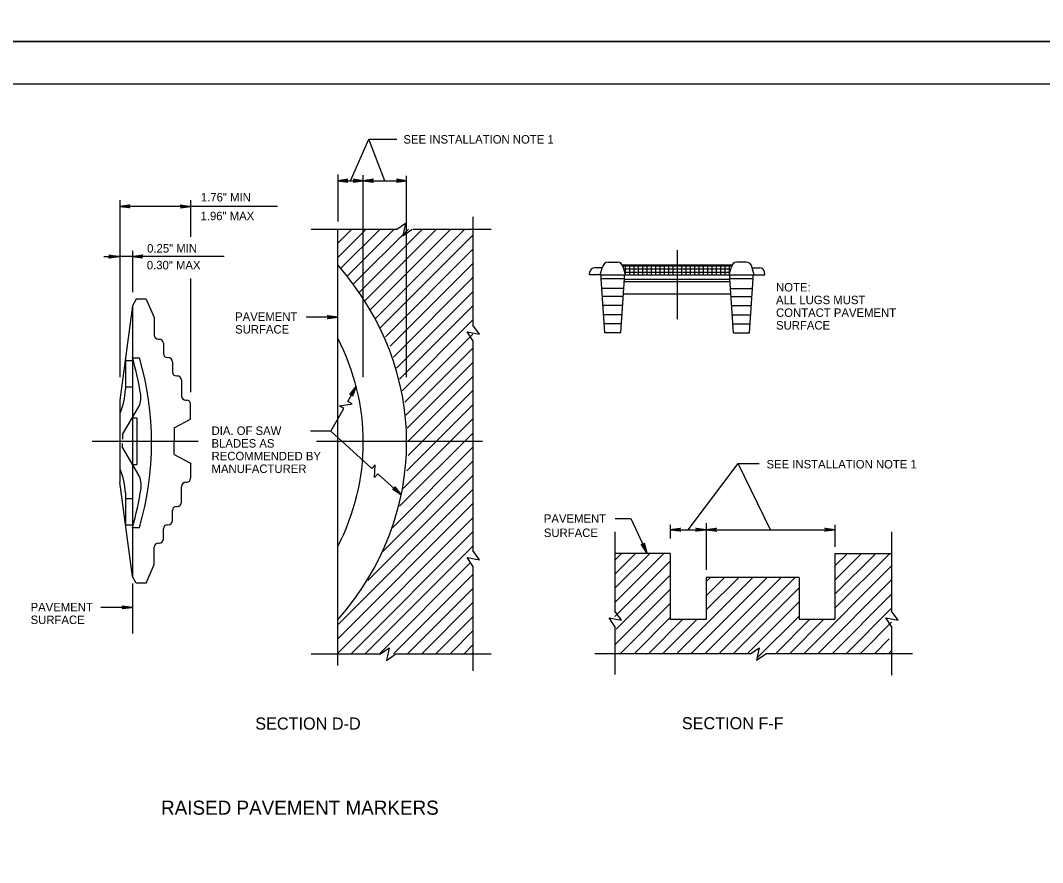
# Model space of a CAD drawing. Extents: x 639362 to 641108, y 298458 to 299646.
# Drawn here: x 640436.9 to 640799.3, y 298760.6 to 299059.1 of the extents above; entities that cross this region are included whole.
import ezdxf

# ---------------------------------------------------------------- set-up
doc = ezdxf.new("R2010")
doc.units = 0
for name, color, linetype in [('1', 7, 'Continuous'), ('2', 7, 'Continuous'), ('PLT-BNDY', 7, 'Continuous')]:
    doc.layers.add(name, color=color, linetype=linetype)

msp = doc.modelspace()

# ---------------------------------------------------------------- linework, layer by layer
at = {"layer": '1'}
msp.add_line((640243.31, 299036.63), (641029.31, 299036.63), dxfattribs=at)
at = {"layer": '2'}
for p, q in [((640553.93, 299002.33), (640560.43, 299017.03)), ((640560.43, 299017.03), (640570.32, 299017.03)), ((640566.15, 299002.33), (640560.43, 299017.03)), ((640549.4, 299004.47), (640549.4, 298987.85)), ((640558.46, 298932.66), (640558.46, 299004.34)), ((640573.84, 298932.66), (640573.84, 299004.07)), ((640549.4, 299002.33), (640558.46, 299002.33)), ((640558.46, 299002.33), (640573.84, 299002.33)), ((640472.13, 298995.38), (640472.13, 298932.71)), ((640497.22, 298995.38), (640497.22, 298982.37)), ((640528.03, 298993.14), (640472.13, 298993.14)), ((640597.33, 298989.51), (640597.33, 298951.16)), ((640539.93, 298985.17), (640570.36, 298985.17)), ((640549.4, 298985.16), (640549.41, 298985.17)), ((640549.4, 298980.15), (640554.42, 298985.17)), ((640549.4, 298975.14), (640559.43, 298985.17)), ((640549.4, 298830.51), (640549.4, 298985.17)), ((640550.44, 298971.18), (640564.44, 298985.17)), ((640552.68, 298968.41), (640569.44, 298985.17)), ((640554.92, 298965.64), (640574.45, 298985.17)), ((640556.84, 298962.55), (640579.46, 298985.17)), ((640558.75, 298959.45), (640584.47, 298985.17)), ((640560.66, 298956.35), (640589.48, 298985.17)), ((640562.56, 298953.25), (640594.49, 298985.17)), ((640570.36, 298985.17), (640573.44, 298987.22)), ((640573.44, 298987.22), (640572.53, 298982.82)), ((640572.53, 298982.82), (640575.83, 298985.17)), ((640576.1, 298985.17), (640603.86, 298985.17)), ((640564.45, 298950.13), (640597.33, 298983.01)), ((640476.61, 298977.46), (640476.61, 298962.86)), ((640566.35, 298947.02), (640597.33, 298978)), ((640669.77, 298977.68), (640669.77, 298953.22)), ((640466.45, 298975.45), (640471.88, 298975.45)), ((640509.08, 298975.45), (640472.13, 298975.45)), ((640645.29, 298973.5), (640648.59, 298973.5)), ((640694.24, 298973.5), (640690.94, 298973.5)), ((640567.97, 298943.62), (640597.33, 298972.99)), ((640638.64, 298969.01), (640638.78, 298969.98)), ((640643.2, 298971.48), (640640.53, 298971.48)), ((640642.5, 298969.01), (640643.19, 298971.43)), ((640650.27, 298972.5), (640689.27, 298972.5)), ((640650.48, 298972.11), (640689.08, 298972.11)), ((640651.38, 298969.01), (640650.68, 298971.43)), ((640651.07, 298971.07), (640688.46, 298971.07)), ((640651.07, 298969.88), (640688.46, 298969.88)), ((640651.36, 298972.11), (640651.36, 298969.01)), ((640652.9, 298972.11), (640652.9, 298969.01)), ((640654.43, 298972.11), (640654.43, 298969.01)), ((640655.96, 298972.11), (640655.96, 298969.01)), ((640657.5, 298972.11), (640657.5, 298969.01)), ((640659.03, 298972.11), (640659.03, 298969.01)), ((640660.56, 298972.11), (640660.56, 298969.01)), ((640662.1, 298972.11), (640662.1, 298969.01)), ((640663.63, 298972.11), (640663.63, 298969.01)), ((640665.17, 298972.11), (640665.17, 298969.01)), ((640666.7, 298972.11), (640666.7, 298969.01)), ((640668.23, 298972.11), (640668.23, 298969.01)), ((640669.77, 298972.11), (640669.77, 298969.01)), ((640671.3, 298972.11), (640671.3, 298969.01)), ((640672.83, 298972.11), (640672.83, 298969.01)), ((640674.36, 298972.11), (640674.36, 298969.01)), ((640675.9, 298972.11), (640675.9, 298969.01)), ((640677.43, 298972.11), (640677.43, 298969.01)), ((640678.97, 298972.11), (640678.97, 298969.01)), ((640680.5, 298972.11), (640680.5, 298969.01)), ((640682.03, 298972.11), (640682.03, 298969.01)), ((640683.57, 298972.11), (640683.57, 298969.01)), ((640685.1, 298972.11), (640685.1, 298969.01)), ((640686.63, 298972.11), (640686.63, 298969.01)), ((640688.15, 298969.01), (640688.85, 298971.43)), ((640688.17, 298972.11), (640688.17, 298969.01)), ((640696.33, 298971.48), (640699, 298971.48)), ((640697.03, 298969.01), (640696.33, 298971.43)), ((640700.89, 298969.01), (640700.75, 298969.98)), ((640497.22, 298967.65), (640497.22, 298927.34)), ((640569.13, 298939.78), (640597.33, 298967.98)), ((640642.75, 298969.01), (640638.64, 298969.01)), ((640642.5, 298969.01), (640651.38, 298969.01)), ((640642.79, 298967.68), (640642.79, 298969.01)), ((640644.12, 298948.4), (640642.79, 298967.68)), ((640642.79, 298967.68), (640651.09, 298967.68)), ((640649.77, 298948.4), (640651.09, 298967.68)), ((640651.01, 298966.54), (640688.52, 298966.54)), ((640651.07, 298967.46), (640688.46, 298967.46)), ((640651.09, 298967.68), (640651.09, 298969.01)), ((640651.13, 298969.01), (640688.4, 298969.01)), ((640688.15, 298969.01), (640697.03, 298969.01)), ((640688.44, 298967.68), (640688.44, 298969.01)), ((640689.77, 298948.4), (640688.44, 298967.68)), ((640688.44, 298967.68), (640696.74, 298967.68)), ((640695.41, 298948.4), (640696.74, 298967.68)), ((640696.74, 298967.68), (640696.74, 298969.01)), ((640696.78, 298969.01), (640700.89, 298969.01)), ((640570.29, 298935.93), (640597.33, 298962.97)), ((640650.84, 298964.12), (640643.03, 298964.12)), ((640688.68, 298964.12), (640696.5, 298964.12)), ((640477.94, 298960.33), (640476.61, 298957.95)), ((640481.5, 298960.33), (640477.94, 298960.33)), ((640481.5, 298960.33), (640484.36, 298953.79)), ((640650.65, 298961.26), (640643.23, 298961.26)), ((640650.71, 298962.2), (640688.82, 298962.2)), ((640688.88, 298961.26), (640696.3, 298961.26)), ((640476.61, 298957.95), (640472.13, 298924.52)), ((640476.61, 298957.95), (640476.61, 298862.07)), ((640571.3, 298931.94), (640597.33, 298957.97)), ((640650.43, 298958.05), (640643.45, 298958.05)), ((640689.1, 298958.05), (640696.08, 298958.05)), ((640484.36, 298953.79), (640484.36, 298947.61)), ((640549.4, 298953.95), (640538.26, 298953.95)), ((640572.26, 298927.89), (640597.33, 298952.96)), ((640650.21, 298954.83), (640643.68, 298954.83)), ((640689.32, 298954.83), (640695.85, 298954.83)), ((640597.33, 298945.7), (640595.28, 298948.78)), ((640595.28, 298948.78), (640599.68, 298947.87)), ((640599.68, 298947.87), (640597.33, 298951.16)), ((640649.99, 298951.62), (640643.9, 298951.62)), ((640649.77, 298948.4), (640644.12, 298948.4)), ((640689.54, 298951.62), (640695.63, 298951.62)), ((640689.77, 298948.4), (640695.41, 298948.4)), ((640485.82, 298946.15), (640486.12, 298946.15)), ((640487.58, 298944.69), (640487.58, 298941.1)), ((640573.15, 298923.77), (640597.33, 298947.95)), ((640597.33, 298945.7), (640597.33, 298871.2)), ((640573.6, 298919.21), (640597.33, 298942.94)), ((640474.15, 298939.56), (640474.15, 298928.37)), ((640474.15, 298938.65), (640476.61, 298938.65)), ((640476.61, 298939.58), (640479.09, 298939.58)), ((640489.04, 298939.64), (640489.33, 298939.64)), ((640490.79, 298938.18), (640490.79, 298934.59)), ((640574.05, 298914.65), (640597.33, 298937.93)), ((640492.25, 298933.12), (640492.54, 298933.12)), ((640494, 298931.66), (640494, 298926.05)), ((640574.48, 298910.07), (640597.33, 298932.92)), ((640474.15, 298929.29), (640476.61, 298929.29)), ((640552.95, 298924.08), (640555.93, 298929.36)), ((640574.32, 298904.91), (640597.33, 298927.91)), ((640472.13, 298924.52), (640472.13, 298895.5)), ((640495.47, 298924.59), (640495.76, 298924.59)), ((640497.22, 298917.76), (640497.22, 298923.13)), ((640550.04, 298922.49), (640554.48, 298923.21)), ((640554.48, 298923.21), (640552.95, 298924.08)), ((640573.89, 298899.46), (640597.33, 298922.91)), ((640473.12, 298912.33), (640478.66, 298921.81)), ((640546.99, 298913.52), (640551.57, 298921.63)), ((640551.57, 298921.63), (640550.04, 298922.49)), ((640476.61, 298918.31), (640478.16, 298918.31)), ((640478.16, 298918.31), (640478.16, 298901.71)), ((640491.46, 298914.75), (640497.22, 298917.76)), ((640572.62, 298893.19), (640597.33, 298917.9)), ((640473.12, 298912.33), (640473.12, 298910.75)), ((640491.46, 298914.75), (640491.46, 298910.01)), ((640546.99, 298913.52), (640539.77, 298913.52)), ((640546.99, 298913.52), (640561.54, 298900.35)), ((640571.36, 298886.91), (640597.33, 298912.89)), ((640462.34, 298910.01), (640499.92, 298910.01)), ((640473.12, 298907.68), (640473.12, 298909.18)), ((640491.46, 298905.27), (640491.46, 298910.01)), ((640541.88, 298910.01), (640600.72, 298910.01)), ((640473.12, 298907.68), (640478.79, 298897.99)), ((640491.46, 298905.27), (640497.22, 298902.26)), ((640568.78, 298879.32), (640597.33, 298907.88)), ((640476.61, 298901.71), (640478.16, 298901.71)), ((640497.22, 298902.26), (640497.22, 298896.89)), ((640562.72, 298901.66), (640561.54, 298900.35)), ((640562.46, 298897.16), (640562.72, 298901.66)), ((640565.39, 298870.93), (640597.33, 298902.87)), ((640673.69, 298878.62), (640691.32, 298902.13)), ((640702.89, 298878.62), (640691.32, 298902.13)), ((640691.32, 298902.13), (640698.87, 298902.13)), ((640560.07, 298860.6), (640597.33, 298897.86)), ((640563.63, 298898.47), (640562.46, 298897.16)), ((640563.63, 298898.47), (640571.91, 298890.98)), ((640476.61, 298862.07), (640472.13, 298895.5)), ((640494, 298888.36), (640494, 298893.97)), ((640495.47, 298895.43), (640495.76, 298895.43)), ((640474.15, 298891.65), (640474.15, 298880.47)), ((640549.4, 298844.92), (640597.33, 298892.85)), ((640474.15, 298889.69), (640476.61, 298889.69)), ((640492.25, 298886.9), (640492.54, 298886.9)), ((640549.4, 298839.91), (640597.33, 298887.85)), ((640490.79, 298881.84), (640490.79, 298885.43)), ((640549.4, 298834.9), (640597.33, 298882.84)), ((640474.15, 298880.34), (640476.61, 298880.34)), ((640476.61, 298879.4), (640479.09, 298879.4)), ((640489.04, 298880.38), (640489.33, 298880.38)), ((640647.82, 298882.56), (640653.38, 298882.56)), ((640653.38, 298882.56), (640659, 298870.44)), ((640667.32, 298880.4), (640667.32, 298875.51)), ((640680.07, 298880.95), (640680.07, 298864.44)), ((640725.71, 298880.4), (640725.71, 298872.49)), ((640487.58, 298875.33), (640487.58, 298878.92)), ((640554.15, 298834.64), (640597.33, 298877.83)), ((640647.65, 298877.84), (640647.65, 298849.8)), ((640667.32, 298878.62), (640680.07, 298878.62)), ((640680.07, 298878.62), (640725.71, 298878.62)), ((640745.78, 298877.84), (640745.78, 298849.8)), ((640484.36, 298866.23), (640484.36, 298872.41)), ((640485.82, 298873.87), (640486.12, 298873.87)), ((640559.16, 298834.64), (640597.33, 298872.82)), ((640597.33, 298865.73), (640595.28, 298868.81)), ((640595.28, 298868.81), (640599.68, 298867.91)), ((640599.68, 298867.91), (640597.33, 298871.2)), ((640667.32, 298870.23), (640647.65, 298870.23)), ((640647.65, 298867.87), (640650.01, 298870.23)), ((640647.65, 298862.86), (640655.02, 298870.23)), ((640647.65, 298857.85), (640660.03, 298870.23)), ((640647.65, 298852.84), (640665.04, 298870.23)), ((640667.32, 298870.23), (640667.32, 298846.76)), ((640725.71, 298870.23), (640725.71, 298846.86)), ((640725.71, 298870.23), (640745.78, 298870.23)), ((640725.71, 298865.79), (640730.15, 298870.23)), ((640725.71, 298860.78), (640735.16, 298870.23)), ((640725.71, 298855.77), (640740.17, 298870.23)), ((640725.71, 298850.77), (640745.18, 298870.23)), ((640481.5, 298859.69), (640484.36, 298866.23)), ((640564.17, 298834.64), (640596.5, 298866.98)), ((640597.33, 298865.73), (640597.33, 298828.63)), ((640647.65, 298847.83), (640667.32, 298867.5)), ((640714.63, 298834.68), (640745.78, 298865.82)), ((640477.94, 298859.69), (640476.61, 298862.07)), ((640569.17, 298834.64), (640597.33, 298862.8)), ((640648.15, 298843.33), (640667.32, 298862.49)), ((640669.56, 298834.68), (640696.61, 298861.73)), ((640674.56, 298834.68), (640701.62, 298861.73)), ((640679.57, 298834.68), (640706.63, 298861.73)), ((640680.07, 298861.73), (640680.07, 298846.86)), ((640712.96, 298861.73), (640680.07, 298861.73)), ((640680.07, 298860.22), (640681.58, 298861.73)), ((640680.07, 298855.21), (640686.59, 298861.73)), ((640680.07, 298850.2), (640691.6, 298861.73)), ((640684.58, 298834.68), (640711.63, 298861.73)), ((640712.96, 298861.73), (640712.96, 298846.76)), ((640476.61, 298859.59), (640476.61, 298841.86)), ((640481.5, 298859.69), (640477.94, 298859.69)), ((640574.18, 298834.64), (640597.33, 298857.79)), ((640647.65, 298837.81), (640667.32, 298857.48)), ((640689.59, 298834.68), (640712.96, 298858.05)), ((640719.64, 298834.68), (640745.78, 298860.81)), ((640724.65, 298834.68), (640745.78, 298855.81)), ((640476.51, 298851.1), (640465.37, 298851.1)), ((640579.19, 298834.64), (640597.33, 298852.78)), ((640649.52, 298834.68), (640667.32, 298852.47)), ((640694.6, 298834.68), (640712.96, 298853.04)), ((640729.66, 298834.68), (640745.78, 298850.8)), ((640584.2, 298834.64), (640597.33, 298847.78)), ((640647.65, 298844.33), (640645.6, 298847.41)), ((640645.6, 298847.41), (640650, 298846.51)), ((640650, 298846.51), (640647.65, 298849.8)), ((640654.53, 298834.68), (640667.32, 298847.47)), ((640659.54, 298834.68), (640671.65, 298846.79)), ((640664.55, 298834.68), (640676.7, 298846.83)), ((640667.32, 298846.86), (640680.07, 298846.86)), ((640698.1, 298833.17), (640712.96, 298848.03)), ((640704.62, 298834.68), (640716.8, 298846.86)), ((640709.62, 298834.68), (640721.8, 298846.86)), ((640712.96, 298846.86), (640725.71, 298846.86)), ((640745.78, 298844.33), (640743.73, 298847.41)), ((640743.73, 298847.41), (640748.13, 298846.51)), ((640748.13, 298846.51), (640745.78, 298849.8)), ((640647.65, 298844.33), (640647.65, 298827.29)), ((640734.67, 298834.68), (640745.78, 298845.79)), ((640745.78, 298844.33), (640745.78, 298827.06)), ((640589.21, 298834.64), (640597.33, 298842.77)), ((640739.68, 298834.68), (640744.9, 298839.89)), ((640564.51, 298834.64), (640567.59, 298836.69)), ((640567.59, 298836.69), (640566.69, 298832.3)), ((640594.22, 298834.64), (640597.33, 298837.76)), ((640695.75, 298834.68), (640698.83, 298836.73)), ((640698.83, 298836.73), (640697.93, 298832.33)), ((640744.68, 298834.68), (640745.78, 298835.77)), ((640539.93, 298834.64), (640564.51, 298834.64)), ((640566.69, 298832.3), (640569.98, 298834.64)), ((640569.98, 298834.64), (640603.86, 298834.64)), ((640596.97, 298834.64), (640597.33, 298834.96)), ((640695.75, 298834.68), (640640.55, 298834.68)), ((640697.93, 298832.33), (640701.22, 298834.68)), ((640753.23, 298834.68), (640701.22, 298834.68))]:
    msp.add_line(p, q, dxfattribs=at)
for points in [[(640552.8, 299002.76), (640552.67, 299002.52), (640549.4, 299002.33), (640552.8, 299002.76), (640552.97, 299002.91), (640549.4, 299002.33), (640552.67, 299002.17), (640552.79, 299001.93), (640549.4, 299002.33), (640552.97, 299001.77), (640552.79, 299001.93)], [(640555.06, 299001.91), (640555.18, 299002.15), (640558.46, 299002.33), (640555.06, 299001.91), (640554.88, 299001.76), (640558.46, 299002.33), (640555.18, 299002.5), (640555.07, 299002.74), (640558.46, 299002.33), (640554.88, 299002.9), (640555.07, 299002.74)], [(640561.87, 299002.76), (640561.74, 299002.52), (640558.46, 299002.33), (640561.87, 299002.76), (640562.04, 299002.91), (640558.46, 299002.33), (640561.73, 299002.17), (640561.85, 299001.93), (640558.46, 299002.33), (640562.04, 299001.77), (640561.85, 299001.93)], [(640570.44, 299001.91), (640570.56, 299002.15), (640573.84, 299002.33), (640570.44, 299001.91), (640570.26, 299001.76), (640573.84, 299002.33), (640570.57, 299002.5), (640570.45, 299002.74), (640573.84, 299002.33), (640570.26, 299002.9), (640570.45, 299002.74)], [(640475.5, 298992.8), (640475.37, 298993.04), (640472.1, 298993.23), (640475.5, 298992.8), (640475.67, 298992.65), (640472.1, 298993.23), (640475.37, 298993.39), (640475.49, 298993.63), (640472.1, 298993.23), (640475.67, 298993.79), (640475.49, 298993.63)], [(640493.81, 298993.57), (640493.94, 298993.32), (640497.22, 298993.14), (640493.81, 298993.57), (640493.64, 298993.72), (640497.22, 298993.14), (640493.94, 298992.98), (640493.82, 298992.73), (640497.22, 298993.14), (640493.64, 298992.57), (640493.82, 298992.73)], [(640468.48, 298975.87), (640468.6, 298975.63), (640471.88, 298975.45), (640468.48, 298975.87), (640468.3, 298976.02), (640471.88, 298975.45), (640468.61, 298975.28), (640468.49, 298975.04), (640471.88, 298975.45), (640468.3, 298974.88), (640468.49, 298975.04)], [(640480.04, 298975), (640479.91, 298975.25), (640476.63, 298975.43), (640480.04, 298975), (640480.21, 298974.85), (640476.63, 298975.43), (640479.91, 298975.59), (640480.03, 298975.83), (640476.63, 298975.43), (640480.21, 298976), (640480.03, 298975.83)], [(640545.99, 298954.38), (640546.12, 298954.13), (640549.4, 298953.95), (640545.99, 298954.38), (640545.82, 298954.53), (640549.4, 298953.95), (640546.12, 298953.78), (640546, 298953.54), (640549.4, 298953.95), (640545.82, 298953.38), (640546, 298953.54)], [(640553.9, 298926.6), (640554.18, 298926.59), (640555.93, 298929.36), (640553.9, 298926.6), (640553.68, 298926.52), (640555.93, 298929.36), (640554.48, 298926.43), (640554.63, 298926.2), (640555.93, 298929.36), (640554.68, 298925.96), (640554.63, 298926.2)], [(640569.66, 298893.57), (640569.58, 298893.3), (640571.91, 298890.98), (640569.66, 298893.57), (640569.62, 298893.79), (640571.91, 298890.98), (640569.36, 298893.04), (640569.11, 298892.94), (640571.91, 298890.98), (640568.86, 298892.94), (640569.11, 298892.94)], [(640670.72, 298878.2), (640670.6, 298878.44), (640667.32, 298878.62), (640670.72, 298878.2), (640670.9, 298878.05), (640667.32, 298878.62), (640670.59, 298878.79), (640670.71, 298879.03), (640667.32, 298878.62), (640670.9, 298879.19), (640670.71, 298879.03)], [(640676.59, 298879.05), (640676.71, 298878.8), (640679.99, 298878.62), (640676.59, 298879.05), (640676.42, 298879.2), (640679.99, 298878.62), (640676.72, 298878.46), (640676.6, 298878.22), (640679.99, 298878.62), (640676.42, 298878.05), (640676.6, 298878.22)], [(640683.47, 298878.2), (640683.35, 298878.44), (640680.07, 298878.62), (640683.47, 298878.2), (640683.65, 298878.04), (640680.07, 298878.62), (640683.34, 298878.79), (640683.46, 298879.03), (640680.07, 298878.62), (640683.65, 298879.19), (640683.46, 298879.03)], [(640722.31, 298879.05), (640722.43, 298878.8), (640725.71, 298878.62), (640722.31, 298879.05), (640722.13, 298879.2), (640725.71, 298878.62), (640722.44, 298878.46), (640722.32, 298878.22), (640725.71, 298878.62), (640722.13, 298878.05), (640722.32, 298878.22)], [(640657.96, 298873.71), (640657.79, 298873.49), (640659, 298870.44), (640657.96, 298873.71), (640658.02, 298873.93), (640659, 298870.44), (640657.48, 298873.34), (640657.21, 298873.35), (640659, 298870.44), (640656.98, 298873.45), (640657.21, 298873.35)], [(640473.1, 298851.53), (640473.23, 298851.28), (640476.51, 298851.1), (640473.1, 298851.53), (640472.93, 298851.68), (640476.51, 298851.1), (640473.23, 298850.94), (640473.11, 298850.7), (640476.51, 298851.1), (640472.93, 298850.53), (640473.11, 298850.7)]]:
    msp.add_lwpolyline(points, dxfattribs=at)
for centre, radius, start, end in [((640640.53, 298969.71), 1.77, 90, 171.2194), ((640698.99, 298969.71), 1.77, 8.7806, 90), ((640485.82, 298947.61), 1.46, 180, 270), ((640486.12, 298944.69), 1.46, 0, 90), ((640489.04, 298941.1), 1.46, 180, 270), ((640372.89, 298909.49), 108, 9.0629, 16.1776), ((640376.74, 298909.49), 106.68, 343.617, 16.384), ((640489.33, 298938.18), 1.46, 0, 90), ((640492.25, 298934.59), 1.46, 180, 270), ((640492.54, 298931.66), 1.46, 0, 90), ((640445.66, 298930.27), 28.55, 338.7062, 356.1981), ((640472.55, 298925.39), 7.08, 329.6797, 9.0629), ((640495.47, 298926.05), 1.46, 180, 270), ((640495.76, 298923.13), 1.46, 0, 90), ((640445.66, 298889.75), 28.55, 3.8019, 21.2938), ((640472.68, 298894.41), 7.08, 351.4083, 30.3164), ((640495.47, 298893.97), 1.46, 90, 180), ((640495.76, 298896.89), 1.46, 270, 0), ((640372.89, 298909.49), 108, 343.8224, 351.4083), ((640492.25, 298885.43), 1.46, 90, 180), ((640492.54, 298888.36), 1.46, 270, 0), ((640489.04, 298878.92), 1.46, 90, 180), ((640489.33, 298881.84), 1.46, 270, 0), ((640485.82, 298872.41), 1.46, 90, 180), ((640486.12, 298875.33), 1.46, 270, 0)]:
    msp.add_arc(centre, radius, start, end, dxfattribs=at)
for centre, major_axis, ratio, start_param, end_param in [((640645.29, 298970.84), (0, 2.66), 0.81, 0, 1.34621), ((640648.58, 298970.84), (0, 2.66), 0.81, 4.937133, 6.283185), ((640690.94, 298970.84), (0, 2.66), 0.81, 0, 1.346052), ((640694.24, 298970.84), (0, 2.66), 0.81, 4.936975, 6.283185), ((640453.3, 298909.56), (120.54, 0), 0.86436, 5.635049, 6.931321), ((640453.3, 298909.56), (105.16, 0), 0.86436, 5.864949, 6.701422)]:
    msp.add_ellipse(centre, major_axis=major_axis, ratio=ratio, start_param=start_param, end_param=end_param, dxfattribs=at)
at = {"layer": 'PLT-BNDY'}
for points in [[(640203.31, 299645.63), (641044.31, 299645.63), (641044.31, 299051.63), (640203.31, 299051.63)], [(640203.31, 299051.63), (641044.31, 299051.63), (641044.31, 298457.63), (640203.31, 298457.63)]]:
    msp.add_lwpolyline(points, close=True, dxfattribs=at)

# ---------------------------------------------------------------- texts
at = {"layer": '2'}
for s, height, p in [('SEE INSTALLATION NOTE 1', 3, (640572.7, 299015.48)), ('1.76" MIN', 3, (640500.87, 298994.97)), ('1.96" MAX', 3, (640500.75, 298988.33)), ('0.25" MIN', 3, (640481.82, 298976.85)), ('0.30" MAX', 3, (640481.71, 298970.91)), ('NOTE:', 3, (640704.81, 298963.06)), ('ALL LUGS MUST ', 3.0001, (640704.81, 298958.56)), ('PAVEMENT', 3, (640513.02, 298952.65)), ('CONTACT PAVEMENT', 3.0001, (640704.81, 298954.06)), ('SURFACE', 3, (640704.81, 298949.56)), ('SURFACE', 3, (640513.02, 298948.15)), ('DIA. OF SAW', 3, (640504.67, 298912.22)), ('BLADES AS', 3, (640504.67, 298907.72)), ('RECOMMENDED BY', 3, (640504.67, 298903.22)), ('MANUFACTURER', 3, (640504.67, 298898.72)), ('SEE INSTALLATION NOTE 1', 3, (640701.43, 298900.34)), ('PAVEMENT', 3, (640622.48, 298881.09)), ('SURFACE', 3, (640622.48, 298876.03)), ('PAVEMENT', 3, (640440.51, 298849.68)), ('SURFACE', 3, (640440.51, 298845.18)), ('SECTION D-D', 4.3, (640520.17, 298807.76)), ('SECTION F-F', 4.3, (640671.41, 298807.87)), ('RAISED PAVEMENT MARKERS', 5, (640486.76, 298777.59))]:
    msp.add_text(s, height=height, dxfattribs=at).set_placement(p)

doc.saveas('drawing.dxf')
